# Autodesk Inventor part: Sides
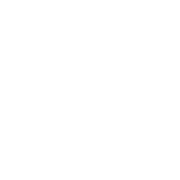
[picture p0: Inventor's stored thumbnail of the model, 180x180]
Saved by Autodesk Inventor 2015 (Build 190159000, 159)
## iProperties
Created: 2016-02
Part Number: Sides
Material: Wood (Birch)
Document SubType Name: Modeling
Designer: Hafliði
Density: 0.55 g/cm^3
Appearance: Birch - Natural Polished
Mass: 330 g
Surface Area: 1300 cm^2
Volume: 600 cm^3
Author: Hafliði
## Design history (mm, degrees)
sketch "Sketch1"
  geometry: L1 (-150, -100)-(150, -100); L2 (150, -100)-(150, 100); L3 (150, 100)-(-150, 100); L4 (-150, 100)-(-150, -100); L5 (-150, -100)-(150, 100); L6 (150, -100)-(-150, 100); 1 further point
  constraints: 12 end point, 2 midpoint, 2 parallel, 1 horizontal, 1 perpendicular
  dimensions: "d0" = 300 distance of L3.end L2.end; "d1" = 200 distance of L2.end L1.end
extrude "Extrusion1" new body sketch "Sketch1" distance "d2" = 10; taper "d3" = 0 deg
body "Solid1"
